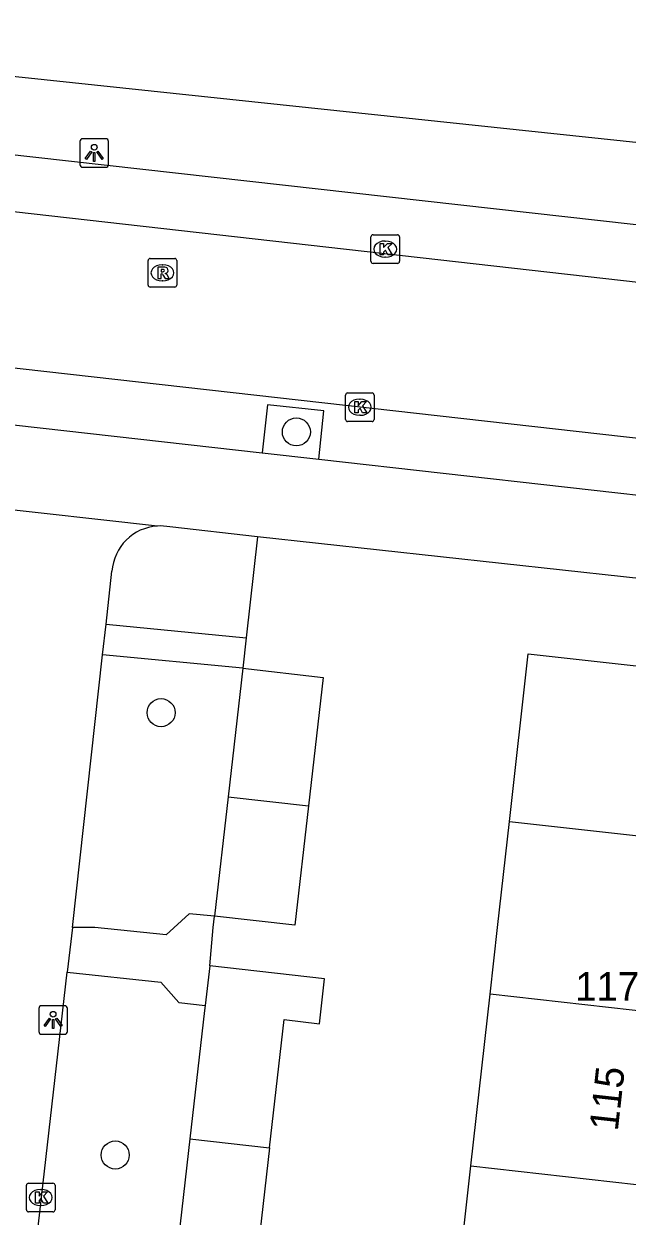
# Model space of a CAD drawing. Extents: x 161928 to 163055, y 386475 to 387428.
# Drawn here: x 162290.09 to 162311.14, y 387239.93 to 387281.54 of the extents above; entities that cross this region are included whole.
import ezdxf

# ---------------------------------------------------------------- set-up
doc = ezdxf.new("R2010")
doc.units = 0
for name, color, linetype in [('IMGEO_Boom', 7, 'Continuous'), ('IMGEO_Groenvoorziening', 7, 'Continuous'), ('IMGEO_Kolk', 7, 'Continuous'), ('IMGEO_Lichtpunt', 7, 'Continuous'), ('IMGEO_Pand', 7, 'Continuous'), ('IMGEO_Pand_nummerreeks', 7, 'Continuous'), ('IMGEO_Parkeervlak_open', 7, 'Continuous'), ('IMGEO_Rijbaan_lokaal_open', 7, 'Continuous'), ('IMGEO_Rioolput', 7, 'Continuous'), ('IMGEO_Voetpad_open', 7, 'Continuous')]:
    doc.layers.add(name, color=color, linetype=linetype)

msp = doc.modelspace()

# ---------------------------------------------------------------- linework, layer by layer
at = {"layer": 'IMGEO_Boom'}
for centre in [(162299.598, 387267.298), (162294.877, 387257.502), (162293.276, 387242.067)]:
    msp.add_circle(centre, 0.489, dxfattribs=at)
at = {"layer": 'IMGEO_Groenvoorziening'}
msp.add_lwpolyline([(162298.238, 387263.643), (162297.847, 387260.112)], dxfattribs=at)
at = {"layer": 'IMGEO_Kolk'}
for p, q in [((162302.199, 387273.253), (162302.199, 387274.105)), ((162302.274, 387274.179), (162303.126, 387274.179)), ((162303.2, 387274.105), (162303.2, 387273.253)), ((162302.687, 387273.959), (162302.712, 387273.959)), ((162302.71, 387273.399), (162302.685, 387273.399)), ((162303.126, 387273.179), (162302.274, 387273.179)), ((162301.387, 387268.659), (162302.239, 387268.659)), ((162301.312, 387267.733), (162301.312, 387268.585)), ((162301.8, 387268.439), (162301.825, 387268.439)), ((162302.313, 387268.585), (162302.313, 387267.733)), ((162301.823, 387267.879), (162301.798, 387267.879)), ((162302.239, 387267.659), (162301.387, 387267.659)), ((162290.177, 387240.157), (162290.177, 387241.009)), ((162290.252, 387241.083), (162291.104, 387241.083)), ((162290.665, 387240.863), (162290.69, 387240.863)), ((162291.178, 387241.009), (162291.178, 387240.157)), ((162291.104, 387240.083), (162290.252, 387240.083)), ((162290.688, 387240.303), (162290.663, 387240.303))]:
    msp.add_line(p, q, dxfattribs=at)
for points in [[(162302.199, 387273.253), (162302.199, 387274.105)], [(162302.274, 387274.179), (162303.126, 387274.179)], [(162303.2, 387274.105), (162303.2, 387273.253)], [(162302.52, 387273.879), (162302.643, 387273.879), (162302.643, 387273.728), (162302.773, 387273.879), (162302.937, 387273.879), (162302.791, 387273.728), (162302.944, 387273.479), (162302.792, 387273.479), (162302.707, 387273.643), (162302.643, 387273.576), (162302.643, 387273.479), (162302.52, 387273.479), (162302.52, 387273.879)], [(162303.126, 387273.179), (162302.274, 387273.179)], [(162301.387, 387268.659), (162302.239, 387268.659)], [(162301.312, 387267.733), (162301.312, 387268.585)], [(162301.633, 387268.359), (162301.756, 387268.359), (162301.756, 387268.208), (162301.886, 387268.359), (162302.05, 387268.359), (162301.904, 387268.208), (162302.057, 387267.959), (162301.905, 387267.959), (162301.82, 387268.123), (162301.756, 387268.056), (162301.756, 387267.959), (162301.633, 387267.959), (162301.633, 387268.359)], [(162302.313, 387268.585), (162302.313, 387267.733)], [(162302.239, 387267.659), (162301.387, 387267.659)], [(162290.177, 387240.157), (162290.177, 387241.009)], [(162290.252, 387241.083), (162291.104, 387241.083)], [(162290.498, 387240.783), (162290.621, 387240.783), (162290.621, 387240.632), (162290.751, 387240.783), (162290.915, 387240.783), (162290.769, 387240.632), (162290.922, 387240.383), (162290.77, 387240.383), (162290.685, 387240.547), (162290.621, 387240.48), (162290.621, 387240.383), (162290.498, 387240.383), (162290.498, 387240.783)], [(162291.178, 387241.009), (162291.178, 387240.157)], [(162291.104, 387240.083), (162290.252, 387240.083)]]:
    msp.add_lwpolyline(points, dxfattribs=at)
for centre, start, end in [((162302.276, 387274.103), 91.552, 178.448), ((162302.276, 387274.103), 91.552, 178.448), ((162303.124, 387274.103), 1.552, 88.448), ((162303.124, 387274.103), 1.552, 88.448), ((162302.276, 387273.255), 181.552, 268.448), ((162302.276, 387273.255), 181.552, 268.448), ((162303.124, 387273.255), 271.552, 358.448), ((162303.124, 387273.255), 271.552, 358.448), ((162301.389, 387268.583), 91.552, 178.448), ((162301.389, 387268.583), 91.552, 178.448), ((162302.237, 387268.583), 1.552, 88.448), ((162302.237, 387268.583), 1.552, 88.448), ((162301.389, 387267.735), 181.552, 268.448), ((162301.389, 387267.735), 181.552, 268.448), ((162302.237, 387267.735), 271.552, 358.448), ((162302.237, 387267.735), 271.552, 358.448), ((162290.254, 387241.007), 91.552, 178.448), ((162290.254, 387241.007), 91.552, 178.448), ((162291.102, 387241.007), 1.552, 88.448), ((162291.102, 387241.007), 1.552, 88.448), ((162290.254, 387240.159), 181.552, 268.448), ((162290.254, 387240.159), 181.552, 268.448), ((162291.102, 387240.159), 271.552, 358.448), ((162291.102, 387240.159), 271.552, 358.448)]:
    msp.add_arc(centre, 0.0765, start, end, dxfattribs=at)
for centre, major_axis, ratio, start_param, end_param in [((162302.686, 387273.679), (-0.387, 0.002), 0.722429, 4.712389, 7.853982), ((162302.711, 387273.679), (-0.39, 0.002), 0.717154, 1.570796, 4.712389), ((162301.799, 387268.159), (-0.387, 0.002), 0.722429, 4.712389, 7.853982), ((162301.824, 387268.159), (-0.39, 0.002), 0.717154, 1.570796, 4.712389), ((162290.664, 387240.583), (-0.387, 0.002), 0.722429, 4.712389, 7.853982), ((162290.689, 387240.583), (-0.39, 0.002), 0.717154, 1.570796, 4.712389)]:
    msp.add_ellipse(centre, major_axis=major_axis, ratio=ratio, start_param=start_param, end_param=end_param, dxfattribs=at)
at = {"layer": 'IMGEO_Lichtpunt'}
for p, q in [((162292.045, 387277.436), (162292.045, 387276.629)), ((162292.045, 387277.436), (162292.045, 387276.629)), ((162292.947, 387277.531), (162292.139, 387277.531)), ((162292.947, 387277.531), (162292.139, 387277.531)), ((162293.041, 387276.629), (162293.041, 387277.436)), ((162293.041, 387276.629), (162293.041, 387277.436)), ((162292.139, 387276.535), (162292.947, 387276.535)), ((162292.139, 387276.535), (162292.947, 387276.535)), ((162290.61, 387247.182), (162290.61, 387246.375)), ((162290.61, 387247.182), (162290.61, 387246.375)), ((162291.512, 387247.277), (162290.704, 387247.277)), ((162291.512, 387247.277), (162290.704, 387247.277)), ((162291.606, 387246.375), (162291.606, 387247.182)), ((162291.606, 387246.375), (162291.606, 387247.182)), ((162290.704, 387246.281), (162291.512, 387246.281)), ((162290.704, 387246.281), (162291.512, 387246.281))]:
    msp.add_line(p, q, dxfattribs=at)
for points in [[(162292.419, 387277.1), (162292.458, 387277.072), (162292.27, 387276.81), (162292.232, 387276.837), (162292.419, 387277.1)], [(162292.521, 387277.052), (162292.568, 387277.052), (162292.568, 387276.73), (162292.521, 387276.73), (162292.521, 387277.052)], [(162292.631, 387277.072), (162292.669, 387277.099), (162292.856, 387276.837), (162292.817, 387276.809), (162292.631, 387277.072)], [(162290.984, 387246.846), (162291.023, 387246.818), (162290.835, 387246.556), (162290.797, 387246.583), (162290.984, 387246.846)], [(162291.086, 387246.798), (162291.133, 387246.798), (162291.133, 387246.476), (162291.086, 387246.476), (162291.086, 387246.798)], [(162291.196, 387246.818), (162291.234, 387246.845), (162291.421, 387246.583), (162291.382, 387246.555), (162291.196, 387246.818)]]:
    msp.add_lwpolyline(points, dxfattribs=at)
for centre in [(162292.544, 387277.234), (162291.109, 387246.98)]:
    msp.add_circle(centre, 0.0994, dxfattribs=at)
for centre, start, end in [((162292.139, 387277.436), 90, 180), ((162292.139, 387277.436), 90, 180), ((162292.947, 387277.436), 0, 90), ((162292.947, 387277.436), 0, 90), ((162292.139, 387276.629), 180, 270), ((162292.139, 387276.629), 180, 270), ((162292.947, 387276.629), 270, 0), ((162292.947, 387276.629), 270, 360), ((162290.704, 387247.182), 90, 180), ((162290.704, 387247.182), 90, 180), ((162291.512, 387247.182), 0, 90), ((162291.512, 387247.182), 0, 90), ((162290.704, 387246.375), 180, 270), ((162290.704, 387246.375), 180, 270), ((162291.512, 387246.375), 270, 0), ((162291.512, 387246.375), 270, 360)]:
    msp.add_arc(centre, 0.0946, start, end, dxfattribs=at)
at = {"layer": 'IMGEO_Pand'}
for points in [[(162307.031, 387253.705), (162307.685, 387259.559), (162315.121, 387258.728), (162314.467, 387252.874)], [(162297.73, 387259.053), (162297.218, 387254.566)], [(162297.73, 387259.053), (162300.533, 387258.733), (162300.022, 387254.253)], [(162297.218, 387254.566), (162296.743, 387250.406)], [(162297.218, 387254.566), (162300.022, 387254.253)], [(162300.022, 387254.253), (162299.546, 387250.086), (162296.743, 387250.406)], [(162306.357, 387247.675), (162306.617, 387250), (162307.031, 387253.705)], [(162307.031, 387253.705), (162314.467, 387252.874)], [(162296.573, 387248.673), (162296.414, 387247.284)], [(162298.66, 387242.319), (162299.17, 387246.79), (162300.403, 387246.649), (162300.582, 387248.215), (162296.573, 387248.673)], [(162305.688, 387241.686), (162306.357, 387247.675)], [(162313.793, 387246.844), (162306.357, 387247.675)], [(162296.414, 387247.284), (162296.394, 387247.107), (162295.883, 387242.629)], [(162295.883, 387242.629), (162295.428, 387238.645)], [(162295.883, 387242.629), (162298.66, 387242.319)], [(162298.66, 387242.319), (162298.204, 387238.328), (162295.428, 387238.645)], [(162305.011, 387235.628), (162305.688, 387241.686)], [(162305.688, 387241.686), (162313.124, 387240.855)]]:
    msp.add_lwpolyline(points, dxfattribs=at)
at = {"layer": 'IMGEO_Parkeervlak_open'}
msp.add_lwpolyline([(162300.378, 387266.344), (162300.553, 387268.039), (162298.588, 387268.238), (162298.409, 387266.566)], dxfattribs=at)
at = {"layer": 'IMGEO_Rijbaan_lokaal_open'}
for points in [[(162319.346, 387271.628), (162271.098, 387277.078)], [(162260.945, 387272.781), (162318.341, 387266.311)]]:
    msp.add_lwpolyline(points, dxfattribs=at)
at = {"layer": 'IMGEO_Rioolput'}
for p, q in [((162294.424, 387272.425), (162294.424, 387273.277)), ((162294.499, 387273.351), (162295.351, 387273.351)), ((162295.425, 387273.277), (162295.425, 387272.425)), ((162294.912, 387273.131), (162294.937, 387273.131)), ((162294.935, 387272.571), (162294.91, 387272.571)), ((162295.351, 387272.351), (162294.499, 387272.351))]:
    msp.add_line(p, q, dxfattribs=at)
for points in [[(162294.424, 387272.425), (162294.424, 387273.277)], [(162294.499, 387273.351), (162295.351, 387273.351)], [(162295.425, 387273.277), (162295.425, 387272.425)], [(162295.013, 387273.049), (162294.761, 387273.051), (162294.761, 387272.651)], [(162294.761, 387272.651), (162294.885, 387272.651), (162294.885, 387272.813), (162294.896, 387272.813)], [(162294.939, 387272.97), (162294.885, 387272.97), (162294.885, 387272.889)], [(162294.885, 387272.889), (162294.937, 387272.889)], [(162294.943, 387272.784), (162295.014, 387272.651), (162295.154, 387272.651), (162295.089, 387272.777)], [(162295.351, 387272.351), (162294.499, 387272.351)]]:
    msp.add_lwpolyline(points, dxfattribs=at)
for centre, radius, start, end in [((162294.501, 387273.275), 0.0765, 91.552, 178.448), ((162294.501, 387273.275), 0.0765, 91.552, 178.448), ((162295.349, 387273.275), 0.0765, 1.552, 88.448), ((162295.349, 387273.275), 0.0765, 1.552, 88.448), ((162294.895, 387272.76), 0.0533, 26.0293, 88.6989), ((162294.921, 387273.078), 0.19, 274.7715, 282.9687), ((162294.945, 387272.874), 0.0964, 77.0061, 93.1865), ((162294.959, 387272.931), 0.0378, 276.6634, 79.6772), ((162295.012, 387272.939), 0.109, 350.3612, 89.416), ((162295.01, 387272.939), 0.112, 277.5842, 350.9817), ((162294.994, 387272.724), 0.108, 29.5134, 73.7905), ((162294.501, 387272.427), 0.0765, 181.552, 268.448), ((162294.501, 387272.427), 0.0765, 181.552, 268.448), ((162295.349, 387272.427), 0.0765, 271.552, 358.448), ((162295.349, 387272.427), 0.0765, 271.552, 358.448)]:
    msp.add_arc(centre, radius, start, end, dxfattribs=at)
for centre, major_axis, ratio, start_param, end_param in [((162294.911, 387272.851), (-0.387, 0.002), 0.722429, 4.712389, 7.853982), ((162294.936, 387272.851), (-0.39, 0.002), 0.717154, 1.570796, 4.712389)]:
    msp.add_ellipse(centre, major_axis=major_axis, ratio=ratio, start_param=start_param, end_param=end_param, dxfattribs=at)
at = {"layer": 'IMGEO_Voetpad_open'}
for points in [[(162319.071, 387276.562), (162314.742, 387277.051), (162272.332, 387281.538)], [(162272.029, 387278.958), (162318.815, 387273.708)], [(162281.146, 387268.509), (162298.409, 387266.566)], [(162298.409, 387266.566), (162300.378, 387266.344)], [(162300.378, 387266.344), (162317.733, 387264.391)], [(162294.752, 387264.014), (162288.705, 387264.679)], [(162298.238, 387263.643), (162295.179, 387263.985)], [(162317.263, 387261.58), (162313.142, 387262.014), (162298.238, 387263.643)], [(162292.957, 387260.587), (162293.162, 387262.437)], [(162292.838, 387259.517), (162292.957, 387260.587)], [(162292.957, 387260.587), (162297.847, 387260.112)], [(162297.847, 387260.112), (162297.73, 387259.053)], [(162291.782, 387250), (162292.838, 387259.517)], [(162297.73, 387259.053), (162292.838, 387259.517)], [(162296.743, 387250.406), (162295.86, 387250.483), (162295.053, 387249.755), (162292.564, 387250), (162291.782, 387250)], [(162296.573, 387248.673), (162296.7, 387250), (162296.743, 387250.406)], [(162291.782, 387250), (162291.605, 387248.45)], [(162290.436, 387238.233), (162291.605, 387248.45)], [(162291.605, 387248.45), (162294.873, 387248.096), (162295.498, 387247.388), (162296.414, 387247.284)]]:
    msp.add_lwpolyline(points, dxfattribs=at)
for centre, radius, start, end in [((162294.854, 387262.321), 1.696, 93.4607, 176.0689), ((162294.851, 387262.314), 1.702, 78.8935, 93.3358)]:
    msp.add_arc(centre, radius, start, end, dxfattribs=at)

# ---------------------------------------------------------------- texts
at = {"layer": 'IMGEO_Pand_nummerreeks'}
msp.add_text('117', height=1, dxfattribs=at).set_placement((162309.329, 387247.448))
msp.add_text('115', height=1, rotation=83.6239, dxfattribs=at).set_placement((162310.814, 387242.879))

doc.saveas('drawing.dxf')
